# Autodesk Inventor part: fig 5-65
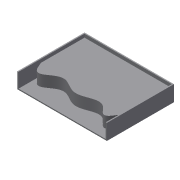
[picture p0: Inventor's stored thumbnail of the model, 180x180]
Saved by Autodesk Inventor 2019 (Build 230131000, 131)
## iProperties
Created: 2004-05
Part Number: fig 5-65
Document SubType Name: Modeling
Designer: CADCIM Technologies
Manufacturer: Standard
Standards Organization: Custom
Density: 1 g/cm^3
Material: Generic
Appearance: Default
Author: CADCIM Technologies
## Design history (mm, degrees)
sketch "Sketch1"
  geometry: L1 (-40, -30)-(40, -30); L2 (40, -30)-(40, 30); L3 (40, 30)-(-40, 30); L4 (-40, 30)-(-40, -30); 1 further point
  constraints: 8 end point, 2 parallel, 1 horizontal, 1 perpendicular, 1 other
  dimensions: "d0" = 80 distance of L1.start L1.end; "d1" = 60 distance of L3.end L1.start; "d2" = 30 distance from line of point (0, 0) L1; "d3" = 40 distance from line of point (0, 0) L4
extrude "Extrusion1" new body sketch "Sketch1" distance "d4" = 14; taper "d5" = 0 deg
shell "Shell1" dims "d6" = 1
workplane "Work Plane1"
sketch "Sketch2"
  geometry: L1 (78, -13)-(78, -11.813); L2 (0, -11.813)-(0, -13); L3 (0, -13)-(78, -13); L4 (0, -11.813)-(17.826, -3.295); L5 (17.826, -3.295)-(60.174, -3.295); L6 (60.174, -3.295)-(78, -11.813); L7 (79, -13.795)-(78, -13.795); L8 (78, 0)-(78, -13) reference; L9 (0, -13)-(0, 0) reference; L10 (78, -13)-(0, -13) reference
  constraints: 14 end point, 3 collinear, 2 equal length, 2 vertical, 1 horizontal alignment, 1 parallel, 1 point on line
extrude "Extrusion2" join sketch "Sketch2" stored distance "d8" = 14; taper "d9" = 0 deg
workplane "Work Plane2"
sketch "Sketch4"
  geometry: 7 further points
  constraints: 7 other
extrude "Extrusion9" join sketch "Sketch4" distance "d35" = 10; taper "d36" = 0 deg
body "Solid1"
other parameters: "d7" = 23, "d18" = 4
